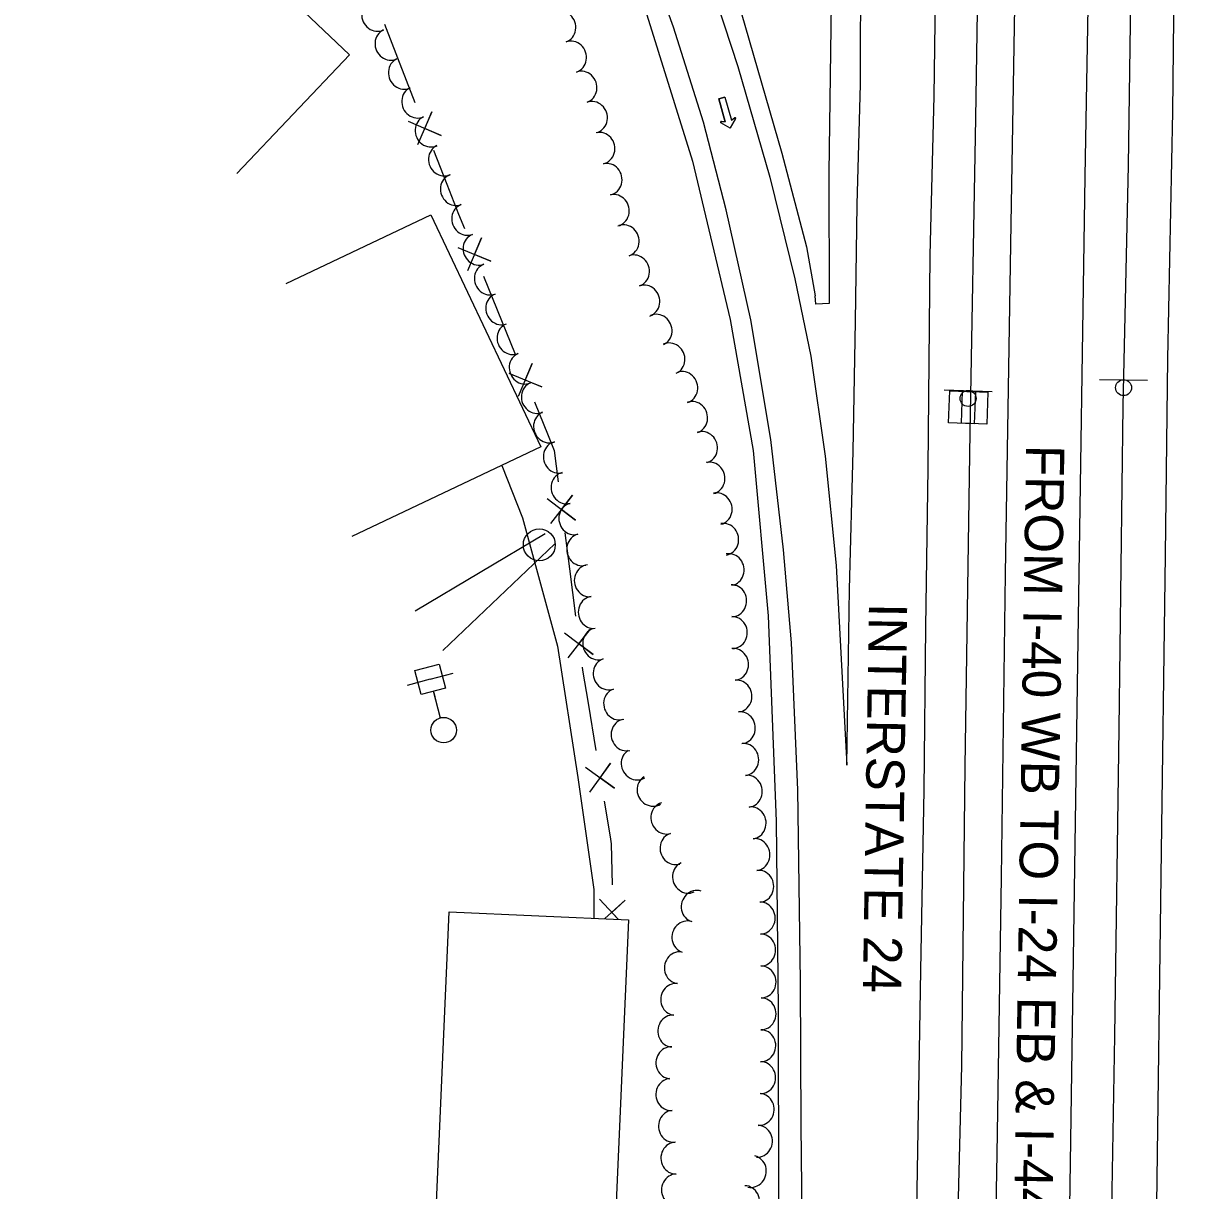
# Model space of a CAD drawing. Extents: x 1746010 to 1754829, y 655801 to 663091.
# Drawn here: x 1753623.6 to 1753991.7, y 656192.5 to 656558.2 of the extents above; entities that cross this region are included whole.
import ezdxf

# ---------------------------------------------------------------- set-up
doc = ezdxf.new("R2010")
doc.units = 0
for name, color, linetype in [('SURVEY - AERIAL SURVEY - Photo Control - Points - Locators', 7, 'Continuous'), ('SURVEY - AERIAL SURVEY - Photo Control - Points - Numbers', 7, 'Continuous'), ('SURVEY - AERIAL SURVEY - Photo Control with Text', 7, 'Continuous'), ('SURVEY - CENTERLINE - Existing Roads - Development', 7, 'Continuous'), ('SURVEY - CENTERLINE - Existing Roads Curve Text', 7, 'Continuous'), ('SURVEY - CENTERLINE - Existing Roads Text', 7, 'Continuous'), ('SURVEY - CENTERLINE - Preliminary - Development', 7, 'Continuous'), ('SURVEY - CONTROL - Points - Numbers', 7, 'Continuous'), ('SURVEY - DRAINAGE - Area Shapes - Points - Elevations', 7, 'Continuous')]:
    doc.layers.add(name, color=color, linetype=linetype)

msp = doc.modelspace()

# ---------------------------------------------------------------- linework, layer by layer
at = {"layer": 'SURVEY - AERIAL SURVEY - Photo Control - Points - Locators'}
for points in [[(1753991.68, 657069.51), (1753989.79, 656994.07), (1753988.51, 656917.34), (1753987.63, 656845.93), (1753986.9, 656777.13), (1753986.19, 656713.33), (1753984.5, 656618.92), (1753983.53, 656530.59), (1753982.02, 656453.23), (1753981.29, 656391.76), (1753979.87, 656290.99), (1753978.52, 656188.25), (1753977.29, 656086), (1753975.64, 655980.75), (1753974.7, 655894.53), (1753973.26, 655807.54)], [(1753945.21, 655807.54), (1753945.71, 655839.43), (1753947.46, 655954.84), (1753949.86, 656090.09), (1753951.64, 656208.18), (1753953.96, 656365.1), (1753956.15, 656510.33), (1753958.33, 656633.76), (1753960.21, 656768.19), (1753961.13, 656897.07), (1753957.75, 656999.64), (1753954.79, 657040.59)], [(1753934.34, 656999.68), (1753937.35, 656928.49), (1753937.83, 656848.86), (1753937.15, 656768.64), (1753935.67, 656669.84), (1753934.34, 656582.14), (1753932.9, 656495.46), (1753931.11, 656385.87), (1753929.83, 656290.6), (1753928.48, 656204.07), (1753926.32, 656083.91), (1753924.94, 655990.25), (1753923.13, 655865.62), (1753922.15, 655807.78)], [(1753911.58, 656971.59), (1753912.64, 656934.08), (1753912.82, 656887.25), (1753912.7, 656839.09), (1753911.76, 656786.44), (1753911.02, 656744.09), (1753910.41, 656695.47), (1753910.01, 656636.87), (1753909.36, 656581.72), (1753908.73, 656535.43), (1753907.55, 656485.64), (1753906.86, 656418.94), (1753906.17, 656369.03), (1753905.58, 656318.08), (1753904.54, 656261.45), (1753903.46, 656192.68), (1753902.26, 656132.87), (1753901.8, 656071.81), (1753900.44, 656014.99), (1753899.79, 655943.06), (1753898.72, 655891.08), (1753897.3, 655813.85), (1753897.22, 655808.04)], [(1753873.7, 656918.81), (1753878.92, 656877.06), (1753880.13, 656859.47), (1753879.47, 656806.65), (1753877.54, 656755.42), (1753876.71, 656705.59), (1753875.89, 656655.77), (1753875.99, 656607.65), (1753876.55, 656564.64), (1753875.84, 656511.45), (1753875.98, 656470.45), (1753871.82, 656470.28), (1753871.62, 656472.92)], [(1753771.59, 656727.52), (1753786.59, 656701.18), (1753800.6, 656673.09), (1753816.65, 656641.34), (1753832.46, 656605.12), (1753848.37, 656561.69), (1753861.15, 656517.6), (1753868.9, 656488.21), (1753871.62, 656472.92)], [(1753750.9, 656709.87), (1753762.28, 656690.3), (1753778.72, 656659.45), (1753799, 656613.54), (1753816.81, 656567.71), (1753833.11, 656515.15), (1753844.95, 656465.51), (1753852.21, 656424.47), (1753856.81, 656372.63), (1753859.37, 656308.23), (1753860.01, 656249.15), (1753860.06, 656189.48), (1753860.62, 656140.29), (1753859.78, 656093.37), (1753859.81, 656047.81), (1753859.08, 655997.53), (1753857.72, 655948.06), (1753857.22, 655896.67), (1753857.34, 655846.8), (1753856.24, 655808.47)], [(1753862.05, 655808.41), (1753862.57, 655841.24), (1753863.76, 655890.45), (1753864.45, 655928.59), (1753865.28, 655971.66), (1753865.87, 656022.61), (1753866.62, 656070.55), (1753866.95, 656126.69), (1753867.66, 656174.28), (1753867.18, 656212.99), (1753867.01, 656258.07), (1753866.19, 656318.05), (1753864.18, 656364.14), (1753861.71, 656393.35), (1753857.69, 656427.83), (1753851.4, 656465.34), (1753843.74, 656499.88), (1753836.64, 656527.31), (1753827.19, 656557.05), (1753815.52, 656589.59), (1753801.88, 656623.23), (1753781.03, 656667.97), (1753768.76, 656691.65), (1753756.51, 656712.8)], [(1753838.67, 656571.33), (1753847.34, 656544.8), (1753857.36, 656510.06), (1753865.26, 656478.24), (1753870.2, 656453.98), (1753874.74, 656422.63), (1753878.13, 656388.37), (1753881.48, 656325.77), (1753882.35, 656380.97), (1753883.5, 656424.22), (1753884.26, 656464.83), (1753884.78, 656501.54), (1753885.79, 656539.28), (1753885.89, 656578.58)], [(1753773.37, 656419.73), (1753779.87, 656403.36), (1753790.82, 656363.14), (1753797.27, 656321.99), (1753802.23, 656286.87), (1753802.22, 656277.88)]]:
    msp.add_lwpolyline(points, dxfattribs=at)
at = {"layer": 'SURVEY - AERIAL SURVEY - Photo Control - Points - Numbers'}
for points in [[(1753959.34, 655807.53), (1753959.92, 655877.58), (1753961.6, 655961.39), (1753962.3, 656049.9), (1753963.82, 656144.04), (1753965.44, 656241.01), (1753966.84, 656337.35), (1753968.08, 656438.44), (1753969.78, 656513.74), (1753971.14, 656610.31), (1753972.49, 656678.9), (1753972.99, 656776.8), (1753973.82, 656865.21), (1753973.77, 656924.3), (1753971.68, 656975.27), (1753968.21, 657018.84), (1753965.85, 657046.35)], [(1753922.72, 656994.79), (1753925.18, 656927.59), (1753925.98, 656864.35), (1753925.56, 656790.71), (1753924.17, 656722.34), (1753923.24, 656622.61), (1753921.81, 656528.59), (1753920.02, 656430.19), (1753918.5, 656325.43), (1753917.39, 656231.6), (1753914.48, 656115.6), (1753913.35, 656013.48), (1753911.14, 655910.91), (1753909.83, 655807.91)]]:
    msp.add_lwpolyline(points, dxfattribs=at)
at = {"layer": 'SURVEY - AERIAL SURVEY - Photo Control with Text'}
for p, q in [((1753960.7, 656446.67), (1753975.7, 656446.46)), ((1753912.02, 656443.42), (1753927.02, 656442.96)), ((1753787.04, 656398.27), (1753746.29, 656374.07)), ((1753754.95, 656361.78), (1753790.04, 656395.14)), ((1753785.17, 656394.83), (1753785.17, 656394.83))]:
    msp.add_line(p, q, dxfattribs=at)
for centre, radius in [((1753968.21, 656444.12), 2.5), ((1753919.49, 656440.74), 2.5), ((1753785.16, 656394.87), 5)]:
    msp.add_circle(centre, radius, dxfattribs=at)
at = {"layer": 'SURVEY - CENTERLINE - Existing Roads - Development'}
for points in [[(1753690.41, 656511.26), (1753725.71, 656548.38), (1753652.71, 656617.78), (1753623.56, 656587.11)], [(1753736.62, 656558.05), (1753740.75, 656547.45)], [(1753740.75, 656547.45), (1753746.2, 656533.49)], [(1753744.1, 656527.61), (1753754.39, 656523.19), (1753749.26, 656525.35), (1753751.52, 656530.54), (1753746.97, 656520.26)], [(1753752.04, 656518.51), (1753756.18, 656507.9)], [(1753756.18, 656507.9), (1753759.85, 656498.49), (1753761.68, 656493.96)], [(1753705.82, 656476.73), (1753751.21, 656498.23), (1753785.63, 656425.53), (1753726.4, 656397.48)], [(1753759.66, 656488.06), (1753770, 656483.77), (1753764.85, 656485.87), (1753767.04, 656491.08), (1753762.62, 656480.75)], [(1753767.71, 656479.06), (1753771.98, 656468.5)], [(1753771.98, 656468.5), (1753777.6, 656454.61)], [(1753775.58, 656448.71), (1753785.92, 656444.42), (1753780.77, 656446.52), (1753782.96, 656451.74), (1753778.54, 656441.4)], [(1753783.63, 656439.71), (1753787.9, 656429.15)], [(1753787.9, 656429.15), (1753789.81, 656424.44), (1753791.08, 656414.61)], [(1753787.64, 656409.42), (1753796.55, 656402.62), (1753792.1, 656405.97), (1753795.54, 656410.45), (1753788.65, 656401.59)], [(1753793.15, 656398.65), (1753794.62, 656387.34)], [(1753794.62, 656387.34), (1753796.54, 656372.46)], [(1753793.1, 656367.28), (1753802.01, 656360.47), (1753797.56, 656363.82), (1753801, 656368.3), (1753794.11, 656359.44)], [(1753798.61, 656356.5), (1753798.73, 656355.63), (1753800.44, 656345.24)], [(1753800.44, 656345.24), (1753802.88, 656330.44)], [(1753799.62, 656325.14), (1753808.76, 656318.64), (1753804.2, 656321.84), (1753807.48, 656326.44), (1753800.9, 656317.34)], [(1753805.5, 656314.56), (1753807.35, 656303.31)], [(1753807.35, 656303.31), (1753807.71, 656301.16), (1753808, 656288.35)], [(1753804.05, 656283.83), (1753809.89, 656277.54)], [(1753809.87, 656277.54), (1753807.87, 656279.67), (1753812.01, 656283.5), (1753805.69, 656277.73)]]:
    msp.add_lwpolyline(points, dxfattribs=at)
msp.add_lwpolyline([(1753813.12, 656277.4), (1753808.9, 656181.45), (1753752.76, 656183.92), (1753756.97, 656279.87)], close=True, dxfattribs=at)
at = {"layer": 'SURVEY - CENTERLINE - Existing Roads Curve Text'}
for p, q in [((1753750.97, 656352.74), (1753743.72, 656350.81)), ((1753750.97, 656352.74), (1753758.22, 656354.66)), ((1753754.2, 656340.56), (1753751.97, 656348.97)), ((1753752.07, 656348.58), (1753752.89, 656345.49))]:
    msp.add_line(p, q, dxfattribs=at)
msp.add_lwpolyline([(1753753.74, 656357.51), (1753755.74, 656349.97), (1753748.2, 656347.97), (1753746.2, 656355.51)], close=True, dxfattribs=at)
msp.add_circle((1753755.2, 656336.79), 4, dxfattribs=at)
at = {"layer": 'SURVEY - CENTERLINE - Existing Roads Text'}
for centre, major_axis in [((1753734.27, 656560.74), (-2.1, 4.54)), ((1753791.87, 656557.18), (1.69, -4.71)), ((1753738.45, 656551.68), (-2.1, 4.54)), ((1753795.22, 656547.76), (1.64, -4.73)), ((1753742.64, 656542.61), (-2.1, 4.54)), ((1753798.49, 656538.31), (1.64, -4.73)), ((1753746.82, 656533.55), (-2.1, 4.54)), ((1753801.76, 656528.86), (1.64, -4.73)), ((1753751.01, 656524.49), (-2.1, 4.54)), ((1753804.12, 656519.15), (1.13, -4.87)), ((1753755.19, 656515.42), (-2.1, 4.54)), ((1753806.37, 656509.4), (1.13, -4.87)), ((1753758.92, 656506.16), (-1.78, 4.67)), ((1753808.63, 656499.66), (1.13, -4.87)), ((1753762.47, 656496.82), (-1.78, 4.67)), ((1753811.72, 656490.18), (1.62, -4.73)), ((1753766.02, 656487.47), (-1.78, 4.67)), ((1753814.95, 656480.74), (1.62, -4.73)), ((1753769.57, 656478.13), (-1.78, 4.67)), ((1753818.19, 656471.3), (1.62, -4.73)), ((1753773.12, 656468.79), (-1.78, 4.67)), ((1753822, 656462.18), (2.05, -4.56)), ((1753776.67, 656459.44), (-1.91, 4.62)), ((1753826.04, 656453.2), (2.05, -4.56)), ((1753780.48, 656450.22), (-1.91, 4.62)), ((1753830.08, 656444.21), (1.56, -4.75)), ((1753784.29, 656441), (-1.91, 4.62)), ((1753833.17, 656434.81), (1.56, -4.75)), ((1753788.11, 656431.78), (-1.91, 4.62)), ((1753836.27, 656425.4), (1.56, -4.75)), ((1753791.17, 656422.33), (-1.21, 4.85)), ((1753838.59, 656415.78), (1.15, -4.87)), ((1753793.58, 656412.68), (-1.21, 4.85)), ((1753840.87, 656406.16), (1.15, -4.87)), ((1753796.01, 656403.02), (-1.23, 4.85)), ((1753842.91, 656396.59), (0.89, -4.92)), ((1753798.46, 656393.32), (-1.23, 4.85)), ((1753844.63, 656387.1), (0.89, -4.92)), ((1753800.83, 656383.61), (-0.61, 4.96)), ((1753845.42, 656377.32), (0.1, -5)), ((1753802.06, 656373.69), (-0.61, 4.96)), ((1753845.61, 656367.36), (0.1, -5)), ((1753803.49, 656363.81), (-1.64, 4.72)), ((1753846.01, 656357.4), (0.53, -4.97)), ((1753806.77, 656354.39), (-1.64, 4.72)), ((1753847.07, 656347.46), (0.53, -4.97)), ((1753810.05, 656344.96), (-1.64, 4.72)), ((1753848.13, 656337.53), (0.53, -4.97)), ((1753812.39, 656335.29), (-1.16, 4.86)), ((1753849.2, 656327.59), (0.53, -4.97)), ((1753815.61, 656326.12), (-2.58, 4.28)), ((1753820.57, 656317.88), (-2.58, 4.28)), ((1753850.33, 656317.66), (0.6, -4.96)), ((1753824.86, 656309.21), (-1.43, 4.79)), ((1753851.52, 656307.73), (0.6, -4.96)), ((1753827.71, 656299.63), (-1.43, 4.79)), ((1753852.72, 656297.8), (0.6, -4.96)), ((1753831.64, 656290.65), (-2.03, 4.57)), ((1753853.92, 656287.87), (0.6, -4.96)), ((1753834.36, 656281.59), (1.46, 4.78)), ((1753854.36, 656277.89), (0.07, -5)), ((1753831.43, 656272.03), (1.46, 4.78)), ((1753854.5, 656267.89), (0.07, -5)), ((1753829.07, 656262.35), (0.58, 4.97)), ((1753854.63, 656257.89), (0.07, -5)), ((1753827.9, 656252.43), (0.58, 4.97)), ((1753854.62, 656247.89), (-0.04, -5)), ((1753826.99, 656242.5), (0.3, 4.99)), ((1753854.55, 656237.89), (-0.04, -5)), ((1753826.4, 656232.55), (0.3, 4.99)), ((1753854.47, 656227.9), (-0.04, -5)), ((1753826.38, 656222.6), (-0.42, 4.98)), ((1753854.04, 656217.93), (-0.27, -4.99)), ((1753827.21, 656212.64), (-0.42, 4.98)), ((1753853.5, 656207.98), (-0.27, -4.99)), ((1753827.96, 656202.67), (-0.09, 5)), ((1753851.56, 656198.48), (-1.11, -4.88)), ((1753828.14, 656192.69), (-0.09, 5)), ((1753849.5, 656189.02), (-0.04, -5))]:
    msp.add_ellipse(centre, major_axis=major_axis, ratio=0.940188, start_param=0, end_param=3.141593, dxfattribs=at)
at = {"layer": 'SURVEY - CENTERLINE - Preliminary - Development'}
for p, q in [((1753917.59, 656437.96), (1753917.59, 656437.96)), ((1753921.57, 656437.86), (1753921.57, 656437.86))]:
    msp.add_line(p, q, dxfattribs=at)
for points in [[(1753913.78, 656443.11), (1753921.78, 656442.8), (1753921.4, 656432.81), (1753913.4, 656433.11), (1753913.78, 656443.11)], [(1753917.74, 656442.98), (1753925.73, 656442.72), (1753925.41, 656432.73), (1753917.42, 656432.99), (1753917.74, 656442.98)]]:
    msp.add_lwpolyline(points, dxfattribs=at)
at = {"layer": 'SURVEY - DRAINAGE - Area Shapes - Points - Elevations'}
for p, q in [((1753841.41, 656534.63), (1753843.3, 656535.16)), ((1753843.3, 656535.16), (1753841.41, 656534.63)), ((1753843.43, 656527.38), (1753841.41, 656534.63)), ((1753841.41, 656534.63), (1753843.43, 656527.38)), ((1753843.3, 656535.16), (1753845.33, 656527.91)), ((1753843.3, 656535.16), (1753845.33, 656527.91)), ((1753845, 656525.41), (1753842.06, 656527.07)), ((1753845, 656525.41), (1753842.06, 656527.07)), ((1753842.21, 656527.53), (1753843.43, 656527.38)), ((1753843.43, 656527.38), (1753842.21, 656527.53)), ((1753846.66, 656528.36), (1753845, 656525.41)), ((1753845, 656525.41), (1753846.66, 656528.36)), ((1753845.33, 656527.91), (1753846.3, 656528.67)), ((1753845.33, 656527.91), (1753846.3, 656528.67))]:
    msp.add_line(p, q, dxfattribs=at)
for centre, start, end in [((1753842.18, 656527.29), 83.1563, 240.6045), ((1753842.18, 656527.29), 83.1563, 240.6045), ((1753846.45, 656528.48), 330.6045, 128.0977), ((1753846.45, 656528.48), 330.6045, 128.0977)]:
    msp.add_arc(centre, 0.246, start, end, dxfattribs=at)

# ---------------------------------------------------------------- texts
at = {"layer": 'SURVEY - CONTROL - Points - Numbers'}
for s, p in [('FROM I-40 WB TO I-24 EB & I-440 WB', (1753937.69, 656426.23)), ('INTERSTATE 24', (1753888.44, 656376.68))]:
    msp.add_text(s, height=12, rotation=269.0994, dxfattribs=at).set_placement(p)

doc.saveas('drawing.dxf')
